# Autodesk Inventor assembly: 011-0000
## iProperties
Created: 2007-02
Part Number: 011-0000
Document SubType Name: Assembly
Designer: GG5883
Project: GDB380
Description: Etau à serrage excentrique
Author: GG5883
Title: ETAU A SERRAGE PAR EXCENTRIQUE
Revision Number: 00
